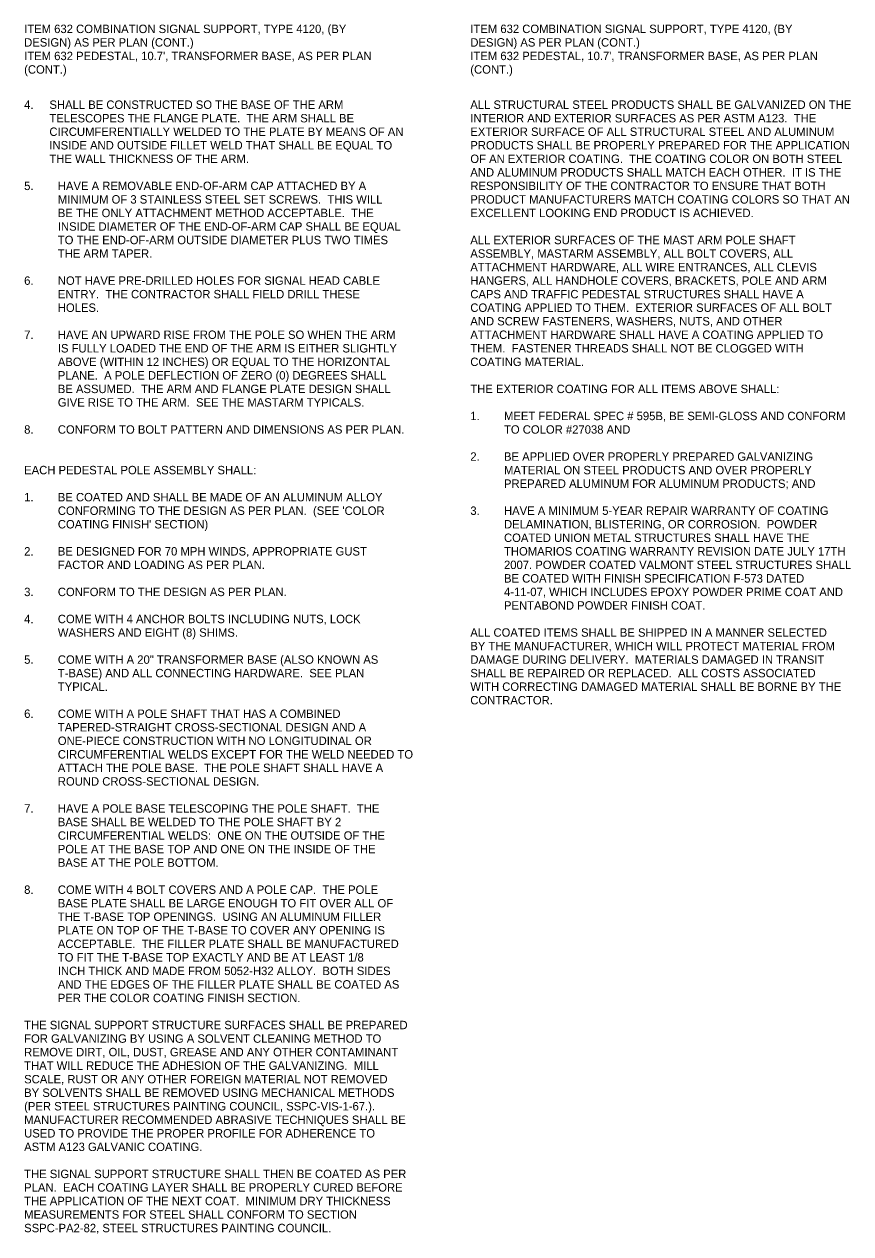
# Model space of a CAD drawing. Extents: x -27 to 74, y -37 to 38.
# Drawn here: x 2.39 to 16.14, y -31.49 to -11.38 of the extents above; entities that cross this region are included whole.
import ezdxf

# ---------------------------------------------------------------- set-up
doc = ezdxf.new("R2010")
doc.units = 0
doc.layers.add('SH_Data', color=7, linetype='Continuous')

msp = doc.modelspace()

# ---------------------------------------------------------------- texts
at = {"layer": 'SH_Data'}
for s, p in [('ITEM 632 COMBINATION SIGNAL SUPPORT, TYPE 4120, (BY ', (2.394, -11.531)), ('ITEM 632 COMBINATION SIGNAL SUPPORT, TYPE 4120, (BY ', (9.814, -11.531)), ('DESIGN) AS PER PLAN (CONT.)', (2.394, -11.756)), ('DESIGN) AS PER PLAN (CONT.)', (9.814, -11.756)), ("ITEM 632 PEDESTAL, 10.7', TRANSFORMER BASE, AS PER PLAN ", (2.394, -11.981)), ("ITEM 632 PEDESTAL, 10.7', TRANSFORMER BASE, AS PER PLAN ", (9.814, -11.981)), ('(CONT.)', (2.394, -12.206)), ('(CONT.)', (9.814, -12.206)), ('4.', (2.394, -12.791)), ('SHALL BE CONSTRUCTED SO THE BASE OF THE ARM ', (2.814, -12.791)), ('ALL STRUCTURAL STEEL PRODUCTS SHALL BE GALVANIZED ON THE ', (9.814, -12.791)), ('TELESCOPES THE FLANGE PLATE.  THE ARM SHALL BE ', (2.814, -13.016)), ('INTERIOR AND EXTERIOR SURFACES AS PER ASTM A123.  THE ', (9.814, -13.016)), ('CIRCUMFERENTIALLY WELDED TO THE PLATE BY MEANS OF AN ', (2.814, -13.241)), ('EXTERIOR SURFACE OF ALL STRUCTURAL STEEL AND ALUMINUM ', (9.814, -13.241)), ('INSIDE AND OUTSIDE FILLET WELD THAT SHALL BE EQUAL TO ', (2.814, -13.466)), ('PRODUCTS SHALL BE PROPERLY PREPARED FOR THE APPLICATION ', (9.814, -13.466)), ('THE WALL THICKNESS OF THE ARM.', (2.814, -13.691)), ('OF AN EXTERIOR COATING.  THE COATING COLOR ON BOTH STEEL ', (9.814, -13.691)), ('AND ALUMINUM PRODUCTS SHALL MATCH EACH OTHER.  IT IS THE ', (9.814, -13.916)), ('5.', (2.394, -14.141)), ('HAVE A REMOVABLE END-OF-ARM CAP ATTACHED BY A ', (2.954, -14.141)), ('RESPONSIBILITY OF THE CONTRACTOR TO ENSURE THAT BOTH ', (9.814, -14.141)), ('MINIMUM OF 3 STAINLESS STEEL SET SCREWS.  THIS WILL ', (2.954, -14.366)), ('PRODUCT MANUFACTURERS MATCH COATING COLORS SO THAT AN ', (9.814, -14.366)), ('BE THE ONLY ATTACHMENT METHOD ACCEPTABLE.  THE ', (2.954, -14.591)), ('EXCELLENT LOOKING END PRODUCT IS ACHIEVED.', (9.814, -14.591)), ('INSIDE DIAMETER OF THE END-OF-ARM CAP SHALL BE EQUAL ', (2.954, -14.816)), ('TO THE END-OF-ARM OUTSIDE DIAMETER PLUS TWO TIMES ', (2.954, -15.041)), ('ALL EXTERIOR SURFACES OF THE MAST ARM POLE SHAFT ', (9.814, -15.041)), ('THE ARM TAPER.', (2.954, -15.266)), ('ASSEMBLY, MASTARM ASSEMBLY, ALL BOLT COVERS, ALL ', (9.814, -15.266)), ('ATTACHMENT HARDWARE, ALL WIRE ENTRANCES, ALL CLEVIS ', (9.814, -15.491)), ('6.', (2.394, -15.716)), ('NOT HAVE PRE-DRILLED HOLES FOR SIGNAL HEAD CABLE ', (2.954, -15.716)), ('HANGERS, ALL HANDHOLE COVERS, BRACKETS, POLE AND ARM ', (9.814, -15.716)), ('ENTRY.  THE CONTRACTOR SHALL FIELD DRILL THESE ', (2.954, -15.941)), ('CAPS AND TRAFFIC PEDESTAL STRUCTURES SHALL HAVE A ', (9.814, -15.941)), ('HOLES.', (2.954, -16.166)), ('COATING APPLIED TO THEM.  EXTERIOR SURFACES OF ALL BOLT ', (9.814, -16.166)), ('AND SCREW FASTENERS, WASHERS, NUTS, AND OTHER ', (9.814, -16.391)), ('7.', (2.394, -16.616)), ('HAVE AN UPWARD RISE FROM THE POLE SO WHEN THE ARM ', (2.954, -16.616)), ('ATTACHMENT HARDWARE SHALL HAVE A COATING APPLIED TO ', (9.814, -16.616)), ('IS FULLY LOADED THE END OF THE ARM IS EITHER SLIGHTLY ', (2.954, -16.841)), ('THEM.  FASTENER THREADS SHALL NOT BE CLOGGED WITH ', (9.814, -16.841)), ('ABOVE (WITHIN 12 INCHES) OR EQUAL TO THE HORIZONTAL ', (2.954, -17.066)), ('COATING MATERIAL.', (9.814, -17.066)), ('PLANE.  A POLE DEFLECTION OF ZERO (0) DEGREES SHALL ', (2.954, -17.291)), ('BE ASSUMED.  THE ARM AND FLANGE PLATE DESIGN SHALL ', (2.954, -17.516)), ('THE EXTERIOR COATING FOR ALL ITEMS ABOVE SHALL:', (9.814, -17.516)), ('GIVE RISE TO THE ARM.  SEE THE MASTARM TYPICALS.', (2.954, -17.741)), ('1.', (9.814, -17.966)), ('MEET FEDERAL SPEC # 595B, BE SEMI-GLOSS AND CONFORM ', (10.374, -17.966)), ('8.', (2.394, -18.191)), ('CONFORM TO BOLT PATTERN AND DIMENSIONS AS PER PLAN.', (2.954, -18.191)), ('TO COLOR #27038 AND', (10.374, -18.191)), ('2.', (9.814, -18.641)), ('BE APPLIED OVER PROPERLY PREPARED GALVANIZING ', (10.374, -18.641)), ('EACH PEDESTAL POLE ASSEMBLY SHALL:', (2.394, -18.866)), ('MATERIAL ON STEEL PRODUCTS AND OVER PROPERLY ', (10.374, -18.866)), ('PREPARED ALUMINUM FOR ALUMINUM PRODUCTS; AND', (10.374, -19.091)), ('1.', (2.394, -19.316)), ('BE COATED AND SHALL BE MADE OF AN ALUMINUM ALLOY ', (2.954, -19.316)), ("CONFORMING TO THE DESIGN AS PER PLAN.  (SEE 'COLOR ", (2.954, -19.541)), ('3.', (9.814, -19.541)), ('HAVE A MINIMUM 5-YEAR REPAIR WARRANTY OF COATING ', (10.374, -19.541)), ("COATING FINISH' SECTION)", (2.954, -19.766)), ('DELAMINATION, BLISTERING, OR CORROSION.  POWDER ', (10.374, -19.766)), ('COATED UNION METAL STRUCTURES SHALL HAVE THE ', (10.374, -19.991)), ('2.', (2.394, -20.216)), ('BE DESIGNED FOR 70 MPH WINDS, APPROPRIATE GUST ', (2.954, -20.216)), ('THOMARIOS COATING WARRANTY REVISION DATE JULY 17TH ', (10.374, -20.216)), ('FACTOR AND LOADING AS PER PLAN.', (2.954, -20.441)), ('2007. POWDER COATED VALMONT STEEL STRUCTURES SHALL ', (10.374, -20.441)), ('BE COATED WITH FINISH SPECIFICATION F-573 DATED ', (10.374, -20.666)), ('3.', (2.394, -20.891)), ('CONFORM TO THE DESIGN AS PER PLAN.', (2.954, -20.891)), ('4-11-07, WHICH INCLUDES EPOXY POWDER PRIME COAT AND ', (10.374, -20.891)), ('PENTABOND POWDER FINISH COAT.', (10.374, -21.116)), ('4.', (2.394, -21.341)), ('COME WITH 4 ANCHOR BOLTS INCLUDING NUTS, LOCK ', (2.954, -21.341)), ('WASHERS AND EIGHT (8) SHIMS.', (2.954, -21.566)), ('ALL COATED ITEMS SHALL BE SHIPPED IN A MANNER SELECTED ', (9.814, -21.566)), ('BY THE MANUFACTURER, WHICH WILL PROTECT MATERIAL FROM ', (9.814, -21.791)), ('5.', (2.394, -22.016)), ('COME WITH A 20" TRANSFORMER BASE (ALSO KNOWN AS ', (2.954, -22.016)), ('DAMAGE DURING DELIVERY.  MATERIALS DAMAGED IN TRANSIT ', (9.814, -22.016)), ('T-BASE) AND ALL CONNECTING HARDWARE.  SEE PLAN ', (2.954, -22.241)), ('SHALL BE REPAIRED OR REPLACED.  ALL COSTS ASSOCIATED ', (9.814, -22.241)), ('TYPICAL.', (2.954, -22.466)), ('WITH CORRECTING DAMAGED MATERIAL SHALL BE BORNE BY THE ', (9.814, -22.466)), ('CONTRACTOR.', (9.814, -22.691)), ('6.', (2.394, -22.916)), ('COME WITH A POLE SHAFT THAT HAS A COMBINED ', (2.954, -22.916)), ('TAPERED-STRAIGHT CROSS-SECTIONAL DESIGN AND A ', (2.954, -23.141)), ('ONE-PIECE CONSTRUCTION WITH NO LONGITUDINAL OR ', (2.954, -23.366)), ('CIRCUMFERENTIAL WELDS EXCEPT FOR THE WELD NEEDED TO ', (2.954, -23.591)), ('ATTACH THE POLE BASE.  THE POLE SHAFT SHALL HAVE A ', (2.954, -23.816)), ('ROUND CROSS-SECTIONAL DESIGN.', (2.954, -24.041)), ('7.', (2.394, -24.491)), ('HAVE A POLE BASE TELESCOPING THE POLE SHAFT.  THE ', (2.954, -24.491)), ('BASE SHALL BE WELDED TO THE POLE SHAFT BY 2 ', (2.954, -24.716)), ('CIRCUMFERENTIAL WELDS:  ONE ON THE OUTSIDE OF THE ', (2.954, -24.941)), ('POLE AT THE BASE TOP AND ONE ON THE INSIDE OF THE ', (2.954, -25.166)), ('BASE AT THE POLE BOTTOM.', (2.954, -25.391)), ('8.', (2.394, -25.841)), ('COME WITH 4 BOLT COVERS AND A POLE CAP.  THE POLE ', (2.954, -25.841)), ('BASE PLATE SHALL BE LARGE ENOUGH TO FIT OVER ALL OF ', (2.954, -26.066)), ('THE T-BASE TOP OPENINGS.  USING AN ALUMINUM FILLER ', (2.954, -26.291)), ('PLATE ON TOP OF THE T-BASE TO COVER ANY OPENING IS ', (2.954, -26.516)), ('ACCEPTABLE.  THE FILLER PLATE SHALL BE MANUFACTURED ', (2.954, -26.741)), ('TO FIT THE T-BASE TOP EXACTLY AND BE AT LEAST 1/8 ', (2.954, -26.966)), ('INCH THICK AND MADE FROM 5052-H32 ALLOY.  BOTH SIDES ', (2.954, -27.191)), ('AND THE EDGES OF THE FILLER PLATE SHALL BE COATED AS ', (2.954, -27.416)), ('PER THE COLOR COATING FINISH SECTION.', (2.954, -27.641)), ('THE SIGNAL SUPPORT STRUCTURE SURFACES SHALL BE PREPARED ', (2.394, -28.091)), ('FOR GALVANIZING BY USING A SOLVENT CLEANING METHOD TO ', (2.394, -28.316)), ('REMOVE DIRT, OIL, DUST, GREASE AND ANY OTHER CONTAMINANT ', (2.394, -28.541)), ('THAT WILL REDUCE THE ADHESION OF THE GALVANIZING.  MILL ', (2.394, -28.766)), ('SCALE, RUST OR ANY OTHER FOREIGN MATERIAL NOT REMOVED ', (2.394, -28.991)), ('BY SOLVENTS SHALL BE REMOVED USING MECHANICAL METHODS ', (2.394, -29.216)), ('(PER STEEL STRUCTURES PAINTING COUNCIL, SSPC-VIS-1-67.).  ', (2.394, -29.441)), ('MANUFACTURER RECOMMENDED ABRASIVE TECHNIQUES SHALL BE ', (2.394, -29.666)), ('USED TO PROVIDE THE PROPER PROFILE FOR ADHERENCE TO ', (2.394, -29.891)), ('ASTM A123 GALVANIC COATING.', (2.394, -30.116)), ('THE SIGNAL SUPPORT STRUCTURE SHALL THEN BE COATED AS PER ', (2.394, -30.566)), ('PLAN.  EACH COATING LAYER SHALL BE PROPERLY CURED BEFORE ', (2.394, -30.791)), ('THE APPLICATION OF THE NEXT COAT.  MINIMUM DRY THICKNESS ', (2.394, -31.016)), ('MEASUREMENTS FOR STEEL SHALL CONFORM TO SECTION ', (2.394, -31.241)), ('SSPC-PA2-82, STEEL STRUCTURES PAINTING COUNCIL.', (2.394, -31.466))]:
    msp.add_text(s, height=0.14, dxfattribs=at).set_placement(p)

doc.saveas('drawing.dxf')
